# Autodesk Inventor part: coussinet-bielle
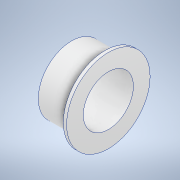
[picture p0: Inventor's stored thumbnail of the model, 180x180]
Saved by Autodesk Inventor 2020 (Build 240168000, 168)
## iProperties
Created: 2023-10
Part Number: coussinet-bielle
Material: Aluminium 6061
Document SubType Name: Modeling
Designer: bruno
Density: 2.7 g/cm^3
Appearance: Aluminium - Plat
Author: bruno
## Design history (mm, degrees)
sketch "Esquisse1"
  geometry: C1 r 2 at (0, 0); C2 r 1.5 at (0, 0); 1 further point
  constraints: 2 centre point, 2 coincident
  dimensions: "d0" = 4 diameter of C1; "d1" = 3 diameter of C2
extrude "Extrusion1" new body sketch "Esquisse1" distance "d2" = 2; taper "d3" = 0 deg
sketch "Esquisse2"
  geometry: C1 r 1.5 at (0, 0) reference; C2 r 2.5 at (0, 0); 1 further point
  constraints: 1 centre point, 1 coincident
  dimensions: "d4" = 5 diameter of C2
extrude "Extrusion2" join sketch "Esquisse2" distance "d5" = 0.2; taper "d6" = 0 deg
node "Solide1"
